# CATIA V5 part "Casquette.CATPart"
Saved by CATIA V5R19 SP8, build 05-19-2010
Part number: Casquette
Bounding box of the stored display mesh (mm): x -2 to 0, y 0 to 180, z 0 to 300
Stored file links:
  D:\Documents\1_Travail\1 - ac-limoges.fr\ac-limoges.fr\Emmanuel Maynard - STI2D_Turgot\1 - IT-I2D\Activités_IT_Première\IT_3_Abris_bus\Maquettes numériques\Abribus_eleve\Casquette.CATPart
  D:\Documents\1_Travail\1 - ac-limoges.fr\ac-limoges.fr\Emmanuel Maynard - STI2D_Turgot\1 - IT-I2D\Activités_IT_Première\IT_3_Abris_bus\Maquettes numériques\Abribus\0-Abribus.CATProduct
  D:\Documents\1_Travail\1 - ac-limoges.fr\ac-limoges.fr\Emmanuel Maynard - STI2D_Turgot\1 - IT-I2D\Activités_IT_Première\IT_3_Abris_bus\Maquettes numériques\Abribus\MakerBeam_300.CATPart
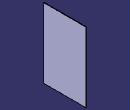
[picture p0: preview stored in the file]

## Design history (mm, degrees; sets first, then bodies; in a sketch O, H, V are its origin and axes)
AxisSystem1: origin (0, 0, 0), X (1, 0, 0), Y (0, 1, 0), Z (0, 0, 1)
Set1
  DatumCurve1
Body1 (main body)
  Sketch1 on YZ plane of AxisSystem1, origin (0, 0, 0), H (0, 1, 0), V (0, 0, 1)
    line L1 (0, 0) -> (180, 0)
    line L2 (180, 0) -> (180, 300)
    line L3 (180, 300) -> (0, 300)
    line L4 (0, 300) -> (0, 0)
    distance L1 L3 = 300
    distance L2 L4 = 180
    horizontal: L1 H, L3 H
    vertical: L2 V, L4 V
  Pad1: profile Sketch1, direction (-1, 0, 0), length 2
